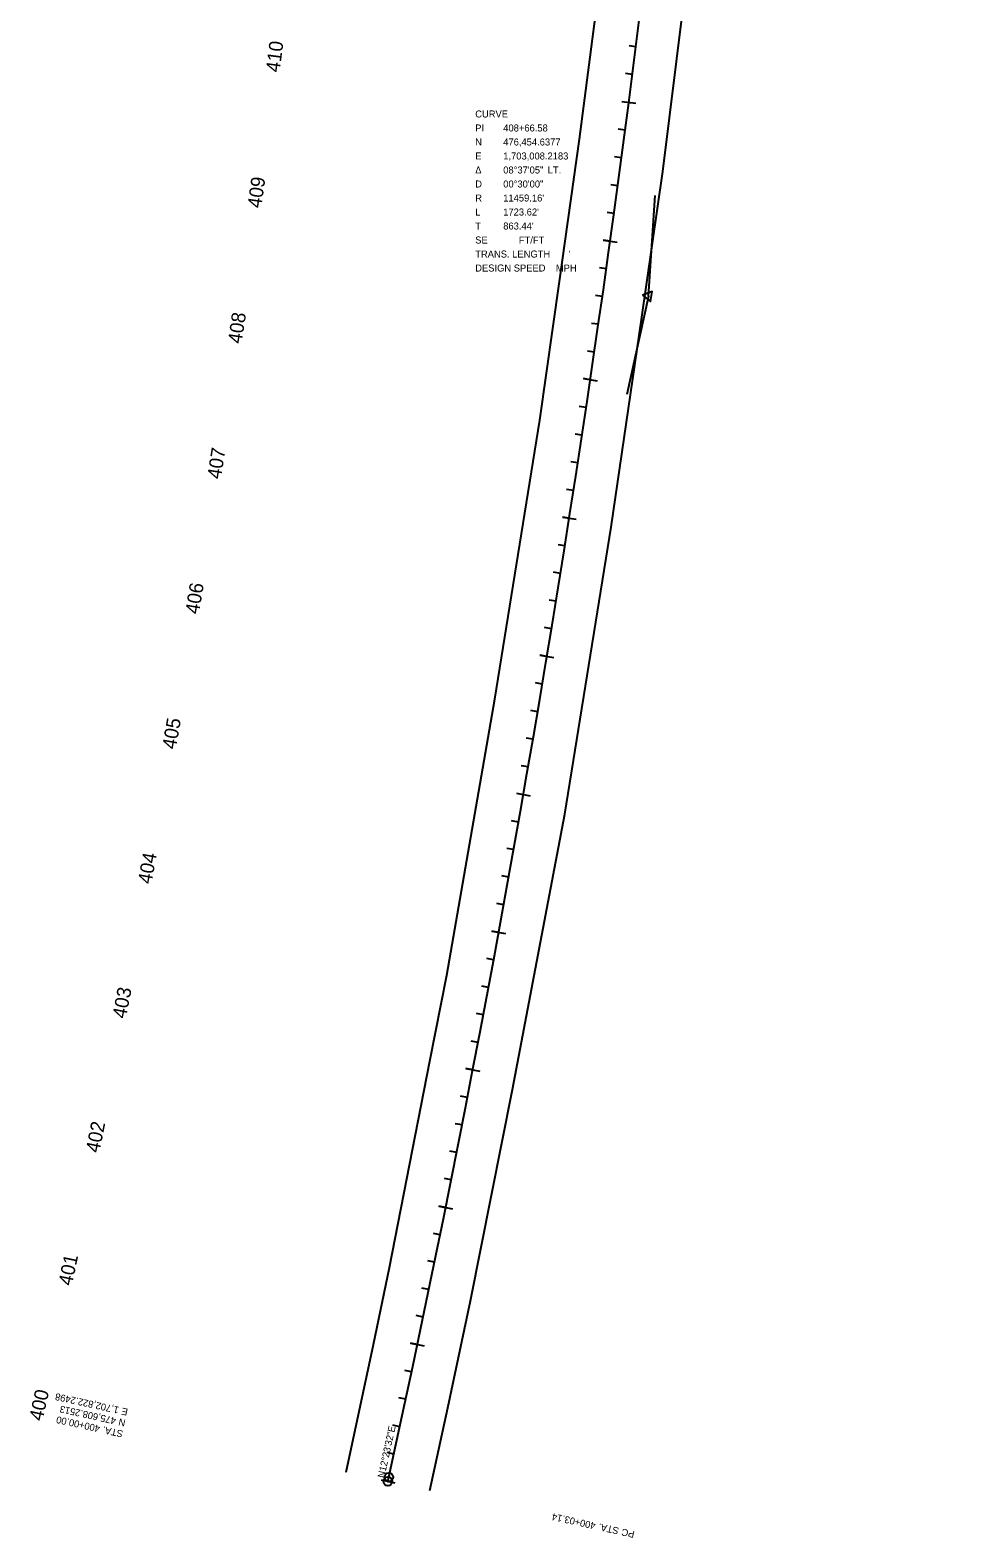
# Model space of a CAD drawing. Extents: x 1699999 to 1705087, y 475568 to 482652.
# Drawn here: x 1702567 to 1703225, y 475568 to 476645 of the extents above; entities that cross this region are included whole.
import ezdxf

# ---------------------------------------------------------------- set-up
doc = ezdxf.new("R2010")
doc.units = 0
for name, color, linetype in [('Default', 7, 'Continuous'), ('DES - DTM - Boundary', 7, 'Continuous'), ('DES - DTM - Ground', 7, 'Continuous'), ('DES - DTM - Points - High', 7, 'Continuous'), ('DESIGN - TYPICAL - Guardrail', 7, 'Continuous'), ('TC_Aggregate', 7, 'Continuous')]:
    doc.layers.add(name, color=color, linetype=linetype)

msp = doc.modelspace()

# ---------------------------------------------------------------- linework, layer by layer
at = {"layer": 'Default'}
msp.add_line((1702822.2, 475608.3), (1702822.9, 475611.3), dxfattribs=at)
msp.add_arc((1691630.7, 478070.5), 11459.2, 347.60785, 356.22594, dxfattribs=at)
at = {"layer": 'DES - DTM - Ground'}
msp.add_line((1702822.2, 475608.3), (1702822.9, 475611.3), dxfattribs=at)
for points in [[(1702792.5, 475614.8), (1702811.9, 475706.1), (1702823.5, 475760.9), (1702852.3, 475908.3), (1702864.3, 475969.8), (1702898.6, 476166.8), (1702930.7, 476366.1), (1702944.7, 476465.1), (1702959.1, 476566.7), (1702978.3, 476715.2), (1702996.2, 476873.4), (1703005.9, 476974.9), (1703015.7, 477085.1), (1703027.3, 477226.9), (1703041.4, 477426.6), (1703058.8, 477682.8), (1703068.5, 477820.5), (1703076.7, 477939.3), (1703102.2, 478346.2), (1703125.6, 478707.3), (1703153.6, 479126.1), (1703182.2, 479545.9), (1703224.8, 480202.3)], [(1702852.1, 475601.7), (1702865.1, 475660.8), (1702881.2, 475737.3), (1702911.2, 475888.1), (1702948.6, 476084.6), (1702981.7, 476289.6), (1703003.2, 476438), (1703018.5, 476543.6), (1703033, 476660.6), (1703046.6, 476770.4), (1703067, 476969.4), (1703076.9, 477065.9), (1703087.8, 477190), (1703103.7, 477439.5), (1703117.2, 477646.5), (1703128.4, 477818.7)]]:
    msp.add_lwpolyline(points, dxfattribs=at)
msp.add_arc((1691630.7, 478070.5), 11459.2, 347.60785, 356.22594, dxfattribs=at)
at = {"layer": 'DES - DTM - Points - High'}
for p, q in [((1702999.3, 476632.7), (1702994.4, 476633.3)), ((1702996.8, 476612.9), (1702991.9, 476613.5)), ((1702989.3, 476593.7), (1702999.2, 476592.4)), ((1702991.7, 476573.2), (1702986.7, 476573.8)), ((1702989, 476553.4), (1702984.1, 476554)), ((1702986.4, 476533.5), (1702981.4, 476534.2)), ((1702983.7, 476513.7), (1702978.7, 476514.4)), ((1702976, 476494.6), (1702985.9, 476493.2)), ((1702978.2, 476474.1), (1702973.2, 476474.8)), ((1702975.4, 476454.3), (1702970.4, 476455)), ((1702972.5, 476434.5), (1702967.6, 476435.2)), ((1702969.7, 476414.7), (1702964.7, 476415.4)), ((1702961.8, 476395.7), (1702971.7, 476394.2)), ((1702963.8, 476375.1), (1702958.9, 476375.9)), ((1702960.8, 476355.4), (1702955.9, 476356.1)), ((1702957.8, 476335.6), (1702952.9, 476336.4)), ((1702954.8, 476315.8), (1702949.8, 476316.6)), ((1702946.8, 476296.8), (1702956.6, 476295.3)), ((1702948.6, 476276.3), (1702943.7, 476277.1)), ((1702945.4, 476256.6), (1702940.5, 476257.4)), ((1702942.2, 476236.8), (1702937.3, 476237.6)), ((1702939, 476217.1), (1702934.1, 476217.9)), ((1702930.8, 476198.2), (1702940.7, 476196.5)), ((1702932.5, 476177.6), (1702927.6, 476178.4)), ((1702929.2, 476157.9), (1702924.3, 476158.7)), ((1702925.8, 476138.2), (1702920.9, 476139)), ((1702922.4, 476118.5), (1702917.5, 476119.3)), ((1702914.1, 476099.6), (1702923.9, 476097.9)), ((1702915.5, 476079.1), (1702910.6, 476079.9)), ((1702912, 476059.4), (1702907.1, 476060.2)), ((1702908.5, 476039.7), (1702903.6, 476040.6)), ((1702905, 476020), (1702900.1, 476020.9)), ((1702896.4, 476001.2), (1702906.3, 475999.4)), ((1702897.7, 475980.7), (1702892.8, 475981.6)), ((1702894.1, 475961), (1702889.2, 475961.9)), ((1702890.4, 475941.3), (1702885.5, 475942.3)), ((1702886.6, 475921.7), (1702881.7, 475922.6)), ((1702878, 475903), (1702887.8, 475901.1)), ((1702879.1, 475882.4), (1702874.2, 475883.4)), ((1702875.2, 475862.8), (1702870.3, 475863.7)), ((1702871.4, 475843.2), (1702866.5, 475844.1)), ((1702867.5, 475823.6), (1702862.6, 475824.5)), ((1702858.6, 475804.9), (1702868.4, 475803)), ((1702859.5, 475784.3), (1702854.7, 475785.3)), ((1702855.5, 475764.7), (1702850.7, 475765.8)), ((1702851.5, 475745.2), (1702846.6, 475746.2)), ((1702847.4, 475725.6), (1702842.5, 475726.6)), ((1702838.4, 475707), (1702848.2, 475705)), ((1702839.2, 475686.4), (1702834.3, 475687.5)), ((1702835, 475666.9), (1702830.1, 475667.9)), ((1702830.8, 475647.3), (1702825.9, 475648.4)), ((1702826.5, 475627.8), (1702821.7, 475628.8)), ((1702817.4, 475609.3), (1702827.1, 475607.2))]:
    msp.add_line(p, q, dxfattribs=at)
at = {"layer": 'DESIGN - TYPICAL - Guardrail'}
for p, q in [((1702989.3, 476593.7), (1702999.2, 476592.4)), ((1702980.9, 476493.9), (1702976, 476494.6)), ((1702966.7, 476394.9), (1702961.8, 476395.7)), ((1702951.7, 476296.1), (1702946.8, 476296.8)), ((1702935.8, 476197.3), (1702930.9, 476198.2)), ((1702914.1, 476099.6), (1702923.9, 476097.9)), ((1702901.4, 476000.3), (1702896.5, 476001.2)), ((1702882.9, 475902.1), (1702878, 475903)), ((1702863.5, 475803.9), (1702858.6, 475804.9)), ((1702843.3, 475706), (1702838.4, 475707)), ((1702817.4, 475609.3), (1702827.2, 475607.2))]:
    msp.add_line(p, q, dxfattribs=at)
for centre, radius in [((1702822.2, 475608.3), 3.14), ((1702822.9, 475611.3), 3.14), ((1702822.2, 475608.3), 0.33), ((1702822.9, 475611.3), 0.33)]:
    msp.add_circle(centre, radius, dxfattribs=at)
at = {"layer": 'TC_Aggregate'}
for q in [(1703013, 476526.5), (1702992.8, 476384.3), (1703008.2, 476454.6)]:
    msp.add_line((1703008.2, 476454.6), q, dxfattribs=at)
msp.add_lwpolyline([(1703004.1, 476455.2), (1703009.8, 476450.8), (1703010.8, 476457.9)], close=True, dxfattribs=at)

# ---------------------------------------------------------------- texts
at = {"layer": 'DES - DTM - Boundary'}
for s, p in [('CURVE    ', (1702884.6, 476582.2)), ('PI', (1702884.6, 476572.2)), ('408+66.58', (1702904.6, 476572.2)), ('N', (1702884.6, 476562.2)), ('476,454.6377', (1702904.6, 476562.2)), ('E', (1702884.6, 476552.2)), ('1,703,008.2183', (1702904.6, 476552.2)), ('Δ', (1702884.6, 476542.2)), ('08°37\'05"', (1702904.6, 476542.2)), (' LT.', (1702934.5, 476542.2)), ('D', (1702884.6, 476532.2)), ('00°30\'00"', (1702904.6, 476532.2)), ('R', (1702884.6, 476522.2)), ("11459.16'", (1702904.6, 476522.2)), ('L', (1702884.6, 476512.2)), ("1723.62'", (1702904.6, 476512.2)), ('T', (1702884.6, 476502.2)), ("863.44'", (1702904.6, 476502.2)), ('SE', (1702884.6, 476492.2)), ('      FT/FT', (1702904.6, 476492.2)), ("TRANS. LENGTH       '", (1702884.6, 476482.2)), ('DESIGN SPEED    MPH', (1702884.6, 476472.2))]:
    msp.add_text(s, height=5, dxfattribs=at).set_placement(p)
for s, p in [('400+03.14', (1702970.9, 475578.8)), (' STA. ', (1702989.3, 475574.8)), ('PC', (1702998.7, 475572.7))]:
    msp.add_text(s, height=4.98, rotation=167.6079, dxfattribs=at).set_placement(p)
at = {"layer": 'DES - DTM - Points - High'}
for s, rotation, p in [('410', 82.5922, (1702744.9, 476614.1)), ('409', 82.0922, (1702731.8, 476517.1)), ('408', 81.5922, (1702717.8, 476420.3)), ('407', 81.0922, (1702703, 476323.6)), ('406', 80.5922, (1702687.3, 476227.1)), ('405', 80.0922, (1702670.8, 476130.6)), ('404', 79.5922, (1702653.4, 476034.4)), ('403', 79.0922, (1702635.2, 475938.3)), ('402', 78.5922, (1702616.2, 475842.4)), ('401', 78.0922, (1702596.6, 475747.5)), ('400', 77.6079, (1702575.7, 475650.9))]:
    msp.add_text(s, height=9.96, rotation=rotation, dxfattribs=at).set_placement(p)
at = {"layer": 'DESIGN - TYPICAL - Guardrail'}
for s, rotation, p in [('410', 82.5922, (1702744.9, 476614.1)), ('405', 80.0922, (1702670.8, 476130.6)), ('400', 77.6079, (1702575.7, 475650.9))]:
    msp.add_text(s, height=9.96, rotation=rotation, dxfattribs=at).set_placement(p)
at = {"layer": 'TC_Aggregate'}
for s, rotation, p in [('1,702,822.2498', 167.6079, (1702630.6, 475661.4)), ('475,608.2513', 167.6079, (1702628.5, 475653.7)), ('E ', 167.6079, (1702637, 475660)), ('400+00.00', 167.6079, (1702617.1, 475648.1)), ('N ', 167.6079, (1702635.3, 475652.2)), ('STA. ', 167.6079, (1702633.6, 475644.4)), ('N12°23\'32"E', 77.6079, (1702819.7, 475610.4))]:
    msp.add_text(s, height=4.98, rotation=rotation, dxfattribs=at).set_placement(p)

doc.saveas('drawing.dxf')
